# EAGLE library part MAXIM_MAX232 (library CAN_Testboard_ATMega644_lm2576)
RS232 TRANSEIVER
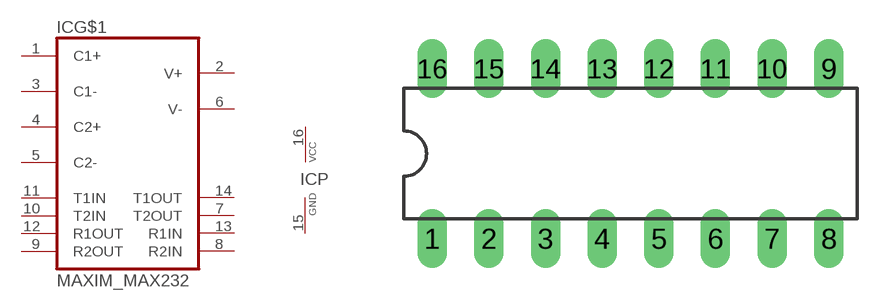
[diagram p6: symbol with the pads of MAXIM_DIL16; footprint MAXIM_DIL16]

Designator prefix IC; gates G$1=MAXIM_MAX232 P=MAXIM_VCC-GND

## MAXIM_MAX232  [MAXIM_DIL16]
1  G$1:C1+
2  G$1:V+
3  G$1:C1-
4  G$1:C2+
5  G$1:C2-
6  G$1:V-
7  G$1:T2OUT  out
8  G$1:R2IN  in
9  G$1:R2OUT  out
10  G$1:T2IN  in
11  G$1:T1IN  in
12  G$1:R1OUT  out
13  G$1:R1IN  in
14  G$1:T1OUT  out
15  P:GND  pwr
16  P:VCC  pwr

## Footprint MAXIM_DIL16 (pad centres in mm)
Dual In Line Package
drill 0.813 long: 1 -8.89,-3.81; 2 -6.35,-3.81; 3 -3.81,-3.81; 4 -1.27,-3.81; 5 1.27,-3.81; 6 3.81,-3.81; 7 6.35,-3.81; 8 8.89,-3.81; 9 8.89,3.81; 10 6.35,3.81; 11 3.81,3.81; 12 1.27,3.81; 13 -1.27,3.81; 14 -3.81,3.81; 15 -6.35,3.81; 16 -8.89,3.81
